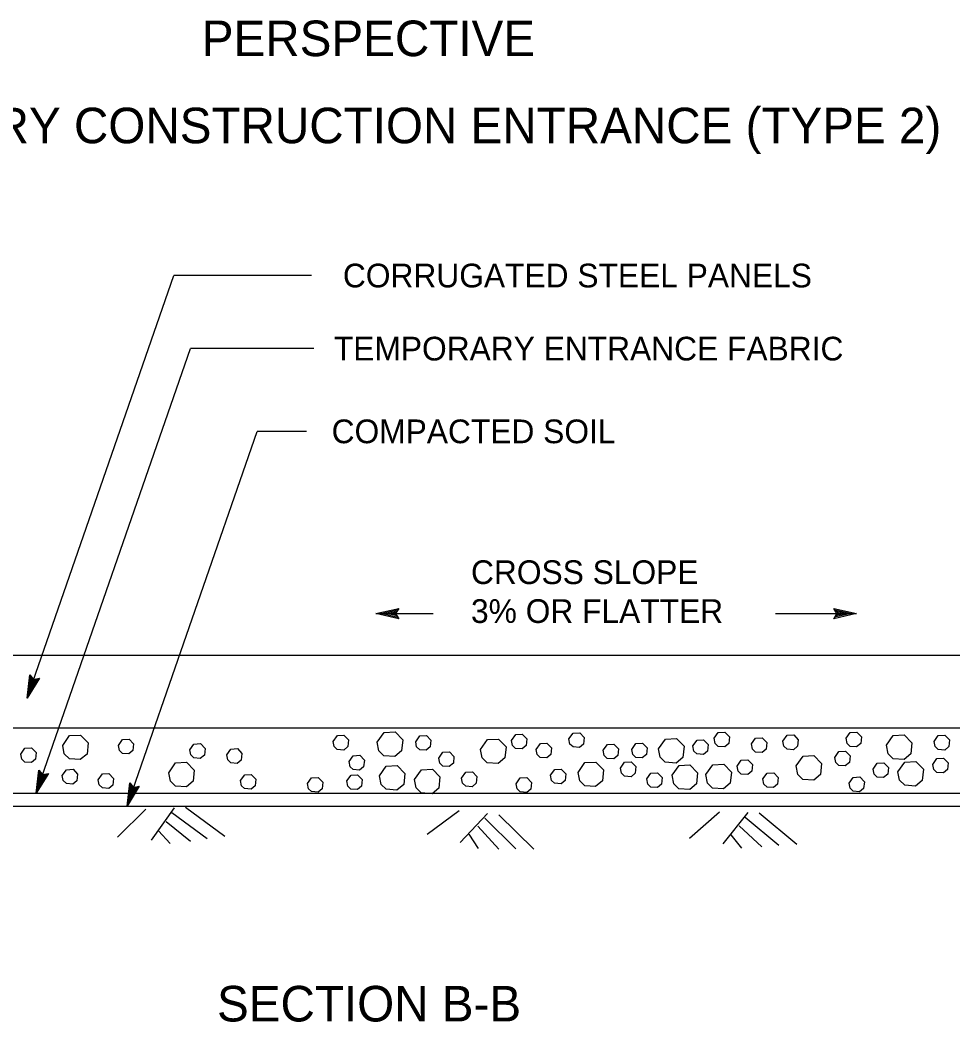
# Model space of a CAD drawing. Extents: x 6709491 to 6710959, y 1869789 to 1870763.
# Drawn here: x 6709685 to 6709920.9, y 1869789.5 to 1870043 of the extents above; entities that cross this region are included whole.
import ezdxf

# ---------------------------------------------------------------- set-up
doc = ezdxf.new("R2010")
doc.units = 0
for name, color, linetype in [('56 Stg 3 Anno', 7, 'Continuous'), ('57 Undefined', 7, 'Continuous'), ('59 Soundwall Ann', 7, 'Continuous'), ('60 Nongeo Data', 7, 'Continuous')]:
    doc.layers.add(name, color=color, linetype=linetype)

msp = doc.modelspace()

# ---------------------------------------------------------------- linework, layer by layer
at = {"layer": '56 Stg 3 Anno'}
for p, q in [((6709686.82, 1869871.46), (6709723.89, 1869978.35)), ((6709758.69, 1869978.35), (6709723.89, 1869978.35)), ((6709689.11, 1869847.39), (6709728.11, 1869959.86)), ((6709759.28, 1869959.86), (6709728.11, 1869959.86)), ((6709712.09, 1869844.14), (6709744.96, 1869938.93)), ((6709757.48, 1869938.93), (6709744.96, 1869938.93)), ((6709775.02, 1869892.82), (6709780.78, 1869894.1)), ((6709776.36, 1869892.82), (6709780.56, 1869893.75)), ((6709780.78, 1869894.1), (6709780.01, 1869892.82)), ((6709780.78, 1869894.1), (6709780.78, 1869894.1)), ((6709891.55, 1869892.82), (6709890.78, 1869894.11)), ((6709890.78, 1869894.11), (6709890.78, 1869894.11)), ((6709890.78, 1869894.11), (6709896.54, 1869892.82)), ((6709890.99, 1869893.76), (6709895.22, 1869892.82)), ((6709775.02, 1869892.82), (6709789.5, 1869892.82)), ((6709780.78, 1869891.53), (6709775.02, 1869892.82)), ((6709775.02, 1869892.82), (6709775.02, 1869892.82)), ((6709780.57, 1869891.87), (6709776.35, 1869892.82)), ((6709777.67, 1869892.82), (6709780.39, 1869893.42)), ((6709780.35, 1869892.22), (6709777.67, 1869892.82)), ((6709779, 1869892.82), (6709780.16, 1869893.07)), ((6709780.18, 1869892.55), (6709779, 1869892.82)), ((6709780.01, 1869892.82), (6709780.78, 1869891.53)), ((6709780.78, 1869891.53), (6709780.78, 1869891.53)), ((6709876.07, 1869892.82), (6709896.54, 1869892.82)), ((6709896.54, 1869892.82), (6709890.78, 1869891.54)), ((6709890.78, 1869891.54), (6709891.55, 1869892.82)), ((6709890.78, 1869891.54), (6709890.78, 1869891.54)), ((6709895.21, 1869892.82), (6709891.01, 1869891.89)), ((6709893.89, 1869892.82), (6709891.18, 1869892.22)), ((6709891.22, 1869893.42), (6709893.89, 1869892.82)), ((6709891.39, 1869893.09), (6709892.57, 1869892.82)), ((6709892.57, 1869892.82), (6709891.41, 1869892.56)), ((6709896.54, 1869892.82), (6709896.54, 1869892.82)), ((6709686.82, 1869871.46), (6709687.5, 1869877.32)), ((6709689.92, 1869876.48), (6709686.82, 1869871.46)), ((6709687.25, 1869872.72), (6709687.75, 1869876.99)), ((6709689.53, 1869876.4), (6709687.25, 1869872.71)), ((6709687.5, 1869877.32), (6709687.5, 1869877.32)), ((6709687.5, 1869877.32), (6709688.45, 1869876.18)), ((6709687.69, 1869873.96), (6709688.01, 1869876.72)), ((6709689.13, 1869876.3), (6709687.69, 1869873.96)), ((6709688.13, 1869875.22), (6709688.26, 1869876.4)), ((6709688.76, 1869876.25), (6709688.13, 1869875.22)), ((6709688.45, 1869876.18), (6709689.92, 1869876.48)), ((6709689.92, 1869876.48), (6709689.92, 1869876.48)), ((6709686.82, 1869871.46), (6709686.82, 1869871.46)), ((6709689.11, 1869847.39), (6709689.79, 1869853.25)), ((6709689.79, 1869853.25), (6709689.79, 1869853.25)), ((6709689.79, 1869853.25), (6709690.75, 1869852.1)), ((6709692.21, 1869852.41), (6709689.11, 1869847.39)), ((6709689.55, 1869848.65), (6709690.04, 1869852.92)), ((6709691.82, 1869852.32), (6709689.55, 1869848.64)), ((6709689.98, 1869849.89), (6709690.3, 1869852.65)), ((6709691.42, 1869852.22), (6709689.98, 1869849.89)), ((6709690.42, 1869851.14), (6709690.56, 1869852.33)), ((6709691.05, 1869852.17), (6709690.42, 1869851.14)), ((6709690.75, 1869852.1), (6709692.21, 1869852.41)), ((6709692.21, 1869852.41), (6709692.21, 1869852.41)), ((6709712.09, 1869844.14), (6709712.77, 1869850)), ((6709715.19, 1869849.16), (6709712.09, 1869844.14)), ((6709712.53, 1869845.4), (6709713.02, 1869849.67)), ((6709714.8, 1869849.08), (6709712.53, 1869845.39)), ((6709712.77, 1869850), (6709712.77, 1869850)), ((6709712.77, 1869850), (6709713.73, 1869848.86)), ((6709712.96, 1869846.65), (6709713.28, 1869849.4)), ((6709714.4, 1869848.98), (6709712.96, 1869846.65)), ((6709713.4, 1869847.9), (6709713.53, 1869849.08)), ((6709714.03, 1869848.93), (6709713.4, 1869847.9)), ((6709713.73, 1869848.86), (6709715.19, 1869849.16)), ((6709715.19, 1869849.16), (6709715.19, 1869849.16)), ((6709689.11, 1869847.39), (6709689.11, 1869847.39)), ((6709712.09, 1869844.14), (6709712.09, 1869844.14))]:
    msp.add_line(p, q, dxfattribs=at)
at = {"layer": '59 Soundwall Ann'}
for p, q in [((6709716.85, 1869843.38), (6709709.67, 1869836.26)), ((6709724, 1869843.72), (6709718.21, 1869835.47)), ((6709726.9, 1869843.84), (6709736.85, 1869836.52)), ((6709796.11, 1869842.93), (6709787.98, 1869836.93)), ((6709723.45, 1869842.5), (6709732.35, 1869835.95)), ((6709803.23, 1869842.23), (6709796.31, 1869834.91)), ((6709802.52, 1869841.1), (6709810.37, 1869833.33)), ((6709806.12, 1869841.93), (6709814.91, 1869833.24)), ((6709861.87, 1869842.56), (6709854.29, 1869835.89)), ((6709869.03, 1869842.48), (6709862.76, 1869834.59)), ((6709868.41, 1869841.29), (6709876.9, 1869834.22)), ((6709871.93, 1869842.43), (6709881.43, 1869834.52)), ((6709720.07, 1869837.85), (6709722.98, 1869834.65)), ((6709722.01, 1869840.23), (6709728.11, 1869835.25)), ((6709800.76, 1869839.07), (6709806.08, 1869833.26)), ((6709866.84, 1869839.12), (6709872.63, 1869833.78)), ((6709798.5, 1869836.99), (6709800.91, 1869833.41)), ((6709864.76, 1869836.85), (6709867.47, 1869833.49))]:
    msp.add_line(p, q, dxfattribs=at)
at = {"layer": '60 Nongeo Data'}
for p, q in [((6709602.72, 1869882.28), (6709947.32, 1869882.28)), ((6709602.72, 1869863.92), (6709756.24, 1869863.92)), ((6709756.24, 1869863.92), (6709947.32, 1869863.92)), ((6709524.37, 1869847.39), (6709755.52, 1869847.39)), ((6709755.52, 1869847.39), (6710030.98, 1869847.39)), ((6709502.72, 1869844.14), (6709754.44, 1869844.14)), ((6709754.44, 1869844.14), (6710047.92, 1869844.14))]:
    msp.add_line(p, q, dxfattribs=at)
for points in [[(6709695.81, 1869859.48), (6709697.55, 1869861.95), (6709700.33, 1869862.11), (6709702.26, 1869860.11), (6709701.98, 1869857.3), (6709700.27, 1869855.88), (6709697.52, 1869856.08), (6709696.23, 1869857.33), (6709695.81, 1869859.48)], [(6709709.89, 1869859.47), (6709710.94, 1869860.95), (6709712.6, 1869861.05), (6709713.76, 1869859.85), (6709713.59, 1869858.16), (6709712.56, 1869857.31), (6709710.92, 1869857.43), (6709710.14, 1869858.18), (6709709.89, 1869859.47)], [(6709764.23, 1869860.47), (6709765.28, 1869861.96), (6709766.94, 1869862.05), (6709768.1, 1869860.85), (6709767.93, 1869859.17), (6709766.9, 1869858.31), (6709765.26, 1869858.43), (6709764.48, 1869859.18), (6709764.23, 1869860.47)], [(6709775.34, 1869860.27), (6709777.08, 1869862.75), (6709779.86, 1869862.9), (6709781.79, 1869860.9), (6709781.51, 1869858.1), (6709779.79, 1869856.67), (6709777.05, 1869856.87), (6709775.76, 1869858.12), (6709775.34, 1869860.27)], [(6709785.07, 1869860.4), (6709786.12, 1869861.89), (6709787.78, 1869861.98), (6709788.94, 1869860.78), (6709788.77, 1869859.1), (6709787.74, 1869858.24), (6709786.1, 1869858.36), (6709785.32, 1869859.11), (6709785.07, 1869860.4)], [(6709801.48, 1869858.47), (6709803.22, 1869860.95), (6709805.99, 1869861.1), (6709807.92, 1869859.1), (6709807.64, 1869856.3), (6709805.93, 1869854.87), (6709803.19, 1869855.07), (6709801.9, 1869856.32), (6709801.48, 1869858.47)], [(6709809.33, 1869860.76), (6709810.37, 1869862.24), (6709812.04, 1869862.34), (6709813.2, 1869861.14), (6709813.03, 1869859.46), (6709812, 1869858.6), (6709810.35, 1869858.72), (6709809.58, 1869859.47), (6709809.33, 1869860.76)], [(6709823.84, 1869861.12), (6709824.89, 1869862.61), (6709826.55, 1869862.7), (6709827.71, 1869861.5), (6709827.54, 1869859.82), (6709826.51, 1869858.97), (6709824.87, 1869859.08), (6709824.09, 1869859.83), (6709823.84, 1869861.12)], [(6709846.49, 1869858.62), (6709848.23, 1869861.09), (6709851, 1869861.25), (6709852.94, 1869859.25), (6709852.66, 1869856.44), (6709850.94, 1869855.02), (6709848.2, 1869855.22), (6709846.91, 1869856.47), (6709846.49, 1869858.62)], [(6709855.17, 1869859.35), (6709856.22, 1869860.83), (6709857.88, 1869860.93), (6709859.04, 1869859.73), (6709858.87, 1869858.04), (6709857.84, 1869857.19), (6709856.2, 1869857.31), (6709855.42, 1869858.06), (6709855.17, 1869859.35)], [(6709860.54, 1869861.28), (6709861.59, 1869862.76), (6709863.26, 1869862.85), (6709864.41, 1869861.65), (6709864.25, 1869859.97), (6709863.22, 1869859.12), (6709861.57, 1869859.23), (6709860.8, 1869859.98), (6709860.55, 1869861.28)], [(6709869.98, 1869859.84), (6709871.02, 1869861.32), (6709872.69, 1869861.42), (6709873.85, 1869860.22), (6709873.68, 1869858.54), (6709872.65, 1869857.68), (6709871, 1869857.8), (6709870.23, 1869858.55), (6709869.98, 1869859.84)], [(6709877.95, 1869860.55), (6709879, 1869862.03), (6709880.66, 1869862.13), (6709881.82, 1869860.93), (6709881.65, 1869859.25), (6709880.62, 1869858.39), (6709878.98, 1869858.51), (6709878.2, 1869859.26), (6709877.95, 1869860.55)], [(6709893.91, 1869861.28), (6709894.95, 1869862.76), (6709896.62, 1869862.85), (6709897.78, 1869861.65), (6709897.61, 1869859.97), (6709896.58, 1869859.12), (6709894.93, 1869859.23), (6709894.16, 1869859.98), (6709893.91, 1869861.28)], [(6709904.11, 1869859.5), (6709905.85, 1869861.97), (6709908.63, 1869862.13), (6709910.56, 1869860.13), (6709910.28, 1869857.32), (6709908.56, 1869855.89), (6709905.82, 1869856.09), (6709904.53, 1869857.35), (6709904.11, 1869859.5)], [(6709916.19, 1869860.47), (6709917.23, 1869861.96), (6709918.9, 1869862.05), (6709920.05, 1869860.85), (6709919.89, 1869859.17), (6709918.86, 1869858.31), (6709917.21, 1869858.43), (6709916.44, 1869859.18), (6709916.19, 1869860.47)], [(6709685.23, 1869857.29), (6709686.28, 1869858.77), (6709687.94, 1869858.87), (6709689.1, 1869857.67), (6709688.93, 1869855.99), (6709687.9, 1869855.13), (6709686.26, 1869855.25), (6709685.48, 1869856), (6709685.23, 1869857.29)], [(6709727.94, 1869858.35), (6709728.98, 1869859.83), (6709730.65, 1869859.93), (6709731.81, 1869858.73), (6709731.64, 1869857.04), (6709730.61, 1869856.19), (6709728.96, 1869856.31), (6709728.19, 1869857.06), (6709727.94, 1869858.35)], [(6709737.28, 1869857.08), (6709738.33, 1869858.57), (6709739.99, 1869858.66), (6709741.15, 1869857.46), (6709740.98, 1869855.78), (6709739.96, 1869854.92), (6709738.31, 1869855.04), (6709737.54, 1869855.79), (6709737.29, 1869857.08)], [(6709815.55, 1869858.46), (6709816.6, 1869859.94), (6709818.26, 1869860.04), (6709819.42, 1869858.84), (6709819.25, 1869857.16), (6709818.23, 1869856.3), (6709816.58, 1869856.42), (6709815.81, 1869857.17), (6709815.56, 1869858.46)], [(6709832.49, 1869858.24), (6709833.54, 1869859.72), (6709835.2, 1869859.82), (6709836.36, 1869858.62), (6709836.19, 1869856.94), (6709835.16, 1869856.08), (6709833.52, 1869856.2), (6709832.74, 1869856.95), (6709832.49, 1869858.24)], [(6709839.71, 1869858.46), (6709840.75, 1869859.94), (6709842.42, 1869860.04), (6709843.57, 1869858.84), (6709843.41, 1869857.16), (6709842.38, 1869856.3), (6709840.73, 1869856.42), (6709839.96, 1869857.17), (6709839.71, 1869858.46)], [(6709768.22, 1869855.39), (6709769.26, 1869856.87), (6709770.93, 1869856.97), (6709772.09, 1869855.77), (6709771.92, 1869854.08), (6709770.89, 1869853.23), (6709769.24, 1869853.35), (6709768.47, 1869854.1), (6709768.22, 1869855.39)], [(6709790.89, 1869856.28), (6709791.94, 1869857.77), (6709793.61, 1869857.86), (6709794.76, 1869856.66), (6709794.6, 1869854.98), (6709793.57, 1869854.12), (6709791.92, 1869854.24), (6709791.15, 1869854.99), (6709790.9, 1869856.28)], [(6709866.37, 1869854.27), (6709867.41, 1869855.75), (6709869.08, 1869855.85), (6709870.24, 1869854.65), (6709870.07, 1869852.96), (6709869.04, 1869852.11), (6709867.39, 1869852.23), (6709866.62, 1869852.98), (6709866.37, 1869854.27)], [(6709881.28, 1869854.29), (6709883.02, 1869856.77), (6709885.79, 1869856.93), (6709887.72, 1869854.92), (6709887.44, 1869852.12), (6709885.73, 1869850.69), (6709882.99, 1869850.89), (6709881.7, 1869852.14), (6709881.28, 1869854.29)], [(6709891.03, 1869856.45), (6709892.07, 1869857.93), (6709893.74, 1869858.02), (6709894.9, 1869856.82), (6709894.73, 1869855.14), (6709893.7, 1869854.29), (6709892.05, 1869854.4), (6709891.28, 1869855.15), (6709891.03, 1869856.45)], [(6709915.85, 1869854.67), (6709916.89, 1869856.15), (6709918.56, 1869856.25), (6709919.71, 1869855.05), (6709919.55, 1869853.36), (6709918.52, 1869852.51), (6709916.87, 1869852.62), (6709916.1, 1869853.38), (6709915.85, 1869854.67)], [(6709695.72, 1869851.85), (6709696.76, 1869853.34), (6709698.43, 1869853.43), (6709699.59, 1869852.23), (6709699.42, 1869850.55), (6709698.39, 1869849.69), (6709696.75, 1869849.81), (6709695.97, 1869850.56), (6709695.72, 1869851.85)], [(6709722.63, 1869852.57), (6709724.37, 1869855.05), (6709727.14, 1869855.21), (6709729.07, 1869853.21), (6709728.8, 1869850.4), (6709727.08, 1869848.97), (6709724.34, 1869849.17), (6709723.05, 1869850.43), (6709722.63, 1869852.57)], [(6709775.89, 1869851.78), (6709777.63, 1869854.25), (6709780.4, 1869854.41), (6709782.33, 1869852.41), (6709782.05, 1869849.6), (6709780.34, 1869848.18), (6709777.6, 1869848.38), (6709776.31, 1869849.63), (6709775.89, 1869851.78)], [(6709784.77, 1869850.86), (6709786.51, 1869853.33), (6709789.29, 1869853.49), (6709791.22, 1869851.49), (6709790.94, 1869848.68), (6709789.22, 1869847.25), (6709786.48, 1869847.45), (6709785.19, 1869848.71), (6709784.77, 1869850.86)], [(6709819.18, 1869851.93), (6709820.22, 1869853.42), (6709821.89, 1869853.51), (6709823.05, 1869852.31), (6709822.88, 1869850.63), (6709821.85, 1869849.77), (6709820.21, 1869849.89), (6709819.43, 1869850.64), (6709819.18, 1869851.93)], [(6709826.13, 1869852.65), (6709827.87, 1869855.13), (6709830.64, 1869855.28), (6709832.57, 1869853.28), (6709832.3, 1869850.48), (6709830.58, 1869849.05), (6709827.84, 1869849.25), (6709826.55, 1869850.5), (6709826.13, 1869852.65)], [(6709836.84, 1869853.73), (6709837.89, 1869855.22), (6709839.55, 1869855.31), (6709840.71, 1869854.11), (6709840.54, 1869852.43), (6709839.52, 1869851.57), (6709837.87, 1869851.69), (6709837.1, 1869852.44), (6709836.84, 1869853.73)], [(6709849.92, 1869851.93), (6709851.66, 1869854.4), (6709854.43, 1869854.56), (6709856.37, 1869852.56), (6709856.09, 1869849.76), (6709854.37, 1869848.33), (6709851.63, 1869848.53), (6709850.34, 1869849.78), (6709849.92, 1869851.93)], [(6709858.44, 1869852.09), (6709860.18, 1869854.56), (6709862.96, 1869854.72), (6709864.89, 1869852.72), (6709864.61, 1869849.91), (6709862.89, 1869848.49), (6709860.15, 1869848.69), (6709858.86, 1869849.94), (6709858.44, 1869852.09)], [(6709900.73, 1869853.51), (6709901.77, 1869855), (6709903.44, 1869855.09), (6709904.6, 1869853.89), (6709904.43, 1869852.21), (6709903.4, 1869851.35), (6709901.76, 1869851.47), (6709900.98, 1869852.22), (6709900.73, 1869853.51)], [(6709907.01, 1869852.8), (6709908.75, 1869855.28), (6709911.52, 1869855.44), (6709913.45, 1869853.43), (6709913.18, 1869850.63), (6709911.46, 1869849.2), (6709908.72, 1869849.4), (6709907.43, 1869850.65), (6709907.01, 1869852.8)], [(6709704.81, 1869850.76), (6709705.86, 1869852.25), (6709707.52, 1869852.34), (6709708.68, 1869851.14), (6709708.52, 1869849.46), (6709707.49, 1869848.6), (6709705.84, 1869848.72), (6709705.07, 1869849.47), (6709704.82, 1869850.76)], [(6709740.79, 1869850.58), (6709741.84, 1869852.07), (6709743.5, 1869852.16), (6709744.66, 1869850.96), (6709744.49, 1869849.28), (6709743.47, 1869848.42), (6709741.82, 1869848.54), (6709741.05, 1869849.29), (6709740.8, 1869850.58)], [(6709757.71, 1869849.82), (6709758.75, 1869851.3), (6709760.42, 1869851.4), (6709761.58, 1869850.2), (6709761.41, 1869848.51), (6709760.38, 1869847.66), (6709758.73, 1869847.78), (6709757.96, 1869848.53), (6709757.71, 1869849.82)], [(6709767.69, 1869850.48), (6709768.73, 1869851.96), (6709770.4, 1869852.06), (6709771.55, 1869850.86), (6709771.39, 1869849.18), (6709770.36, 1869848.32), (6709768.71, 1869848.44), (6709767.94, 1869849.19), (6709767.69, 1869850.48)], [(6709796.7, 1869851.2), (6709797.74, 1869852.69), (6709799.41, 1869852.78), (6709800.57, 1869851.58), (6709800.4, 1869849.9), (6709799.37, 1869849.04), (6709797.72, 1869849.16), (6709796.95, 1869849.91), (6709796.7, 1869851.2)], [(6709810.48, 1869849.75), (6709811.52, 1869851.24), (6709813.19, 1869851.33), (6709814.35, 1869850.13), (6709814.18, 1869848.45), (6709813.15, 1869847.59), (6709811.5, 1869847.71), (6709810.73, 1869848.46), (6709810.48, 1869849.75)], [(6709843.52, 1869850.99), (6709844.56, 1869852.47), (6709846.23, 1869852.57), (6709847.39, 1869851.37), (6709847.22, 1869849.69), (6709846.19, 1869848.83), (6709844.55, 1869848.95), (6709843.77, 1869849.7), (6709843.52, 1869850.99)], [(6709872.89, 1869850.99), (6709873.94, 1869852.48), (6709875.6, 1869852.57), (6709876.76, 1869851.37), (6709876.59, 1869849.69), (6709875.56, 1869848.83), (6709873.92, 1869848.95), (6709873.14, 1869849.7), (6709872.89, 1869850.99)], [(6709894.65, 1869849.92), (6709895.7, 1869851.4), (6709897.36, 1869851.5), (6709898.52, 1869850.29), (6709898.35, 1869848.61), (6709897.33, 1869847.76), (6709895.68, 1869847.87), (6709894.91, 1869848.63), (6709894.66, 1869849.92)]]:
    msp.add_lwpolyline(points, dxfattribs=at)

# ---------------------------------------------------------------- texts
at = {"layer": '57 Undefined'}
for s, height, p in [('PERSPECTIVE', 9, (6709730.99, 1870033.85)), ('TEMPORARY CONSTRUCTION ENTRANCE (TYPE 2)', 9, (6709619.09, 1870011.81)), ('CORRUGATED STEEL PANELS', 6, (6709766.67, 1869975.35)), ('TEMPORARY ENTRANCE FABRIC ', 6, (6709764.39, 1869956.86)), ('COMPACTED SOIL', 6, (6709763.82, 1869935.93)), ('CROSS SLOPE', 6, (6709799.06, 1869900.3)), ('3% OR FLATTER', 6, (6709799.06, 1869890.46)), ('SECTION B-B', 9, (6709734.84, 1869789.64))]:
    msp.add_text(s, height=height, dxfattribs=at).set_placement(p)

doc.saveas('drawing.dxf')
